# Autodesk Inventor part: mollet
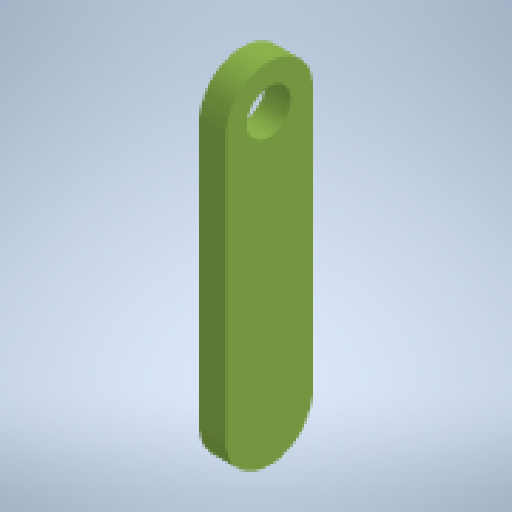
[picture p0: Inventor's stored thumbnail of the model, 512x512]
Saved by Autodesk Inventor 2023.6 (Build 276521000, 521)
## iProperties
Created: 2026-01
Part Number: mollet
Material: Générique
Document SubType Name: Modeling
Designer: mel
Density: 1 g/cm^3
Appearance: Terre battue - Brun foncé
Author: mel
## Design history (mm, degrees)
sketch "Esquisse2"
  geometry: L1 (0, 5)-(-30, 5); L2 (0, -5)-(-30, -5); C1 r 2.5 at (0, 0); A1 r 5 centre (0, 0) between (0, -5) and (0, 5); A2 r 5 centre (-30, 0) between (-30, 5) and (-30, -5); 1 further point
  constraints: 4 end point, 4 point on circle, 4 tangent, 3 centre point, 2 coincident
  dimensions: "d0" = 10 diameter of A1; "d1" = 10 diameter of A2; "d2" = 5 diameter of C1; "d5" = 30 distance of A2.centre point (0, 0)
extrude "Extrusion1" new body sketch "Esquisse2" distance "d3" = 3; taper "d4" = 0 deg
node "Solide1"
